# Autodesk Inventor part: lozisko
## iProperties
Shininess: 64.0
Length Units: 11269
Angle Units: 11279
Time Units: 11290
Mass Units: 11283
Length Display Precision: 3
Angle Display Precision: 2
Compacted: True
Part Number: lozisko
Document SubType Name: Modeling
Created: 2003-06
Material: Výchozí
Designer: rudolf_martonka
Density: 0.0
Volumn: 0.0
Area: 0.0
PropertySet Name: Model Information
Control State: 0
Master: False
Checked Out: False
Title: lozisko
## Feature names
1. Vysunutí1 [Extrusion]
